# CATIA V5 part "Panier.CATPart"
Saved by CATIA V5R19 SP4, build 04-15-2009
Part number: Panier
Bounding box of the stored display mesh (mm): x -135 to 0, y -124 to 124, z -124 to 124
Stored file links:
  G:\EU_thinkMotion\CFAO_2010\SIL_groupe2\SIL_groupe2\msauret\Brevet_Sauret_parametre\Panier.CATPart
  F:\Brevet_Sauret paramétré\Product3.CATProduct
  G:\EU_thinkMotion\CFAO_2010\SIL_groupe2\SIL_groupe2\msauret\Brevet_Sauret_parametre\squelette.CATPart
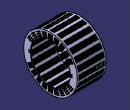
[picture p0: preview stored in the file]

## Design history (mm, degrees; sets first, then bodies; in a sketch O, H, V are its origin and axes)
Set1
  Plane1 to Plane5: linked copy from another document
  Line1: linked copy from another document
  Line2: linked copy from another document
Body1 (main body)
  Sketch1 on Plane1, origin (0, 0, 0), H (0, 1, 0), V (0, 0, 1)
    circle A1 centre (0, 0) radius 124
    point P1 (0, 0)
    coincidence: P1 V
  Pad1: profile Sketch1, direction (1, 0, 0), up to Plane2
  Sketch2 on Plane1, origin (0, 0, 0), H (0, 1, 0), V (0, 0, 1)
    circle A1 centre (0, 0) radius 120
  Pocket1: profile Sketch2, direction (-1, 0, 0), up to Plane3
  Sketch3 on Plane1, origin (0, 0, 0), H (0, 1, 0), V (0, 0, 1)
    circle A1 centre (0, 0) radius 120
  Pad2: profile Sketch3, direction (1, 0, 0), up to Plane4
  Sketch4 on Plane1, origin (0, 0, 0), H (0, 1, 0), V (0, 0, 1)
    arc A1 centre (0, 0) radius 93 from (92.9353, 3.4677) to (-92.9353, 3.4677) ccw
    point P1 (0, 0)
    line L1 (92.9353, 3.4677) -> (100, 7)
    point P2 (100, 7)
    line L2 (100, 7) -> (100, -7)
    point P3 (100, -7)
    line L3 (100, -7) -> (92.9353, -3.4677)
    point P4 (92.9353, 3.4677)
    point P5 (92.9353, -3.4677)
    point P6 (-100, 7)
    point P7 (-92.9353, 3.4677)
    line L4 (-92.9353, 3.4677) -> (-100, 7)
    point P8 (-100, -7)
    line L5 (-100, 7) -> (-100, -7)
    point P9 (-92.9353, -3.4677)
    line L6 (-100, -7) -> (-92.9353, -3.4677)
    arc A2 centre (0, 0) radius 93 from (-92.9353, -3.4677) to (92.9353, -3.4677) ccw
    coincidence: P1 H, A1 A2
    vertical: L2 V
    symmetry: P2 P6 V, P4 P7 V, L1 L4 V, P3 P8 V, L2 L5 V, P5 P9 V, L3 L6 V
  Pocket2: profile Sketch4, direction (-1, 0, 0), up to Plane4
  Sketch5 on Plane5, origin (0, 0, 124), H (1, 0, 0), V (0, 1, 0)
    line L1 (-127, 10) -> (-122, 10)
    line L2 (-122, 10) -> (-122, -10)
    line L3 (-122, -10) -> (-127, -10)
    line L4 (-127, -10) -> (-127, 10)
    reference projected line E1 (-135, 124) -> (-135, -124) from edge [end face of Pad1 | face of Pad1 from Sketch1.A1]
    distance L4 E1 = 8
    horizontal: L1 H, L3 H
    vertical: L2 V, L4 V
  Pocket3: profile Sketch5, direction (0, 0, -1), through (limit type 6)
  RectPattern1: of Pocket3, direction 1 instances 20, spacing 6, along Line1
  CircPattern1: of RectPattern1, instances 24, angular step 15, axis from Line1
  Sketch6 on Plane2, origin (-135, 0, 0), H (0, 1, 0), V (0, 0, 1)
    line L1 (-10, 116) -> (10, 116)
    line L2 (10, 116) -> (10, 112)
    line L3 (10, 112) -> (-10, 112)
    line L4 (-10, 112) -> (-10, 116)
    reference intersected line E1 through (0, 124) direction (-1, 0) from Plane5
    distance E1 L1 = 8
    horizontal: L1 H, L3 H
    vertical: L2 V, L4 V
  Pocket4: profile Sketch6, direction (-1, 0, 0), through (limit type 6)
  RectPattern2: of Pocket4, direction 1 instances 3, spacing 8, along Line2
  CircPattern2: of RectPattern2, instances 24, angular step 15, axis from Line1
  Sketch7 on Plane1, origin (0, 0, 0), H (0, 1, 0), V (0, 0, 1)
    line L1 (-10, 116) -> (10, 116)
    line L2 (10, 116) -> (10, 112)
    line L3 (10, 112) -> (-10, 112)
    line L4 (-10, 112) -> (-10, 116)
    reference intersected line E1 through (0, 124) direction (-1, 0) from Plane5
    distance L1 E1 = 8
    horizontal: L1 H, L3 H
    vertical: L2 V, L4 V
  Pocket5: profile Sketch7, direction (-1, 0, 0), through (limit type 6)
  RectPattern3: of Pocket5, direction 1 instances 3, spacing 8, along Line2
  CircPattern3: of RectPattern3, instances 5, angular step 15, axis from Line1
  CircPattern4: of RectPattern3, instances 5, angular step 15, axis from Line1
  Sketch8 on Plane1, origin (0, 0, 0), H (0, 1, 0), V (0, 0, 1)
    line L1 (-10, -112) -> (10, -112)
    line L2 (10, -112) -> (10, -116)
    line L3 (10, -116) -> (-10, -116)
    line L4 (-10, -116) -> (-10, -112)
    reference projected circle E1 centre (0, 0) radius 124 from edge [face of Pad1 from Sketch1.A1 | start face of Pad1]
    distance E1 L3 = 8
    horizontal: L1 H, L3 H
    vertical: L2 V, L4 V
  Pocket6: profile Sketch8, direction (-1, 0, 0), through (limit type 6)
  RectPattern4: of Pocket6, direction 1 instances 3, spacing 8, along Line2 reversed
  CircPattern5: of RectPattern4, instances 5, angular step 15, axis from Line1
  CircPattern6: of RectPattern4, instances 5, angular step 15, axis from Line1
  Sketch9 on face of Pad1, origin (0, 0, 0), H (0, 1, 0), V (0, 0, 1)
    circle A1 centre (0, 0) radius 124
    point P1 (0, 0)
    coincidence: P1 V
  Pad3: profile Sketch9, direction (1, 0, 0), up to Plane2
  Sketch10 on face of Pad1, origin (0, 0, 0), H (0, 1, 0), V (0, 0, 1)
    circle A1 centre (0, 0) radius 124
    point P1 (0, 0)
    coincidence: P1 V
  Pad4: profile Sketch10, direction (1, 0, 0), up to Plane2
  Sketch11 on face of Pad4, origin (0, 0, 0), H (0, 1, 0), V (0, 0, 1)
    circle A1 centre (0, 0) radius 124
    point P1 (0, 0)
    coincidence: P1 V
  Pad5: profile Sketch11, direction (1, 0, 0), up to Plane2
Current feature: CircPattern6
